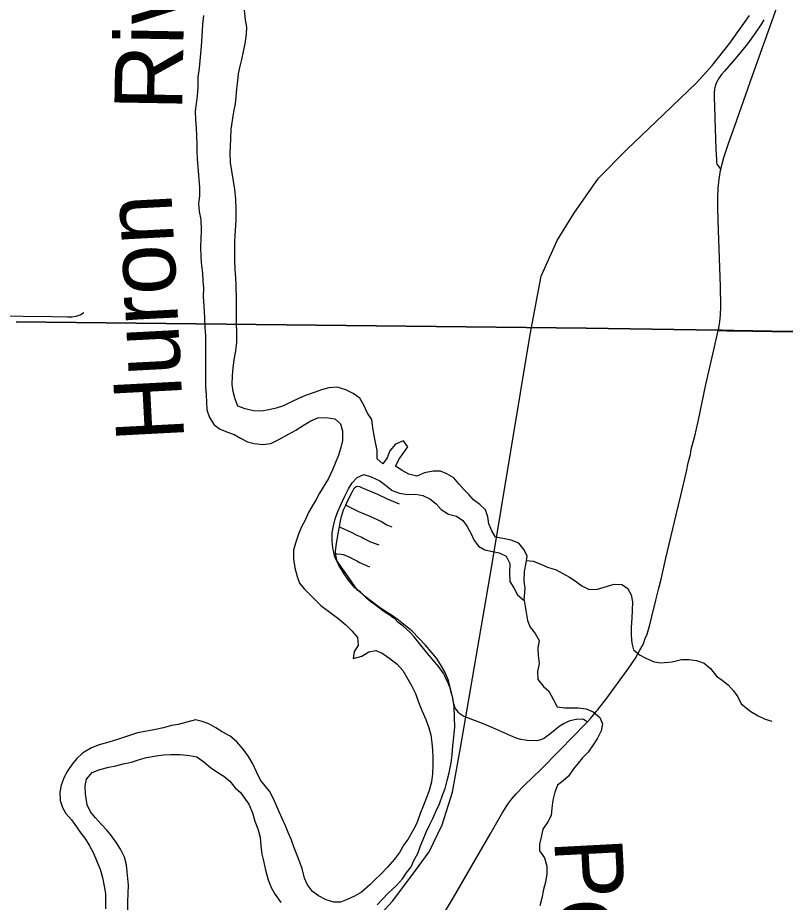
# Model space of a CAD drawing. Extents: x 0 to 34, y 0 to 22.
# Drawn here: x 3.171 to 4.241, y 16.061 to 17.296 of the extents above; entities that cross this region are included whole.
import ezdxf

# ---------------------------------------------------------------- set-up
doc = ezdxf.new("R2010")
doc.units = 0
for name, color, linetype in [('GM_X_Corporation', 7, 'Continuous'), ('GM_X_County_Road', 7, 'Continuous'), ('GM_X_Major_River', 7, 'Continuous'), ('GM_X_Major_River_Text', 7, 'Continuous'), ('GM_X_Minor_River', 7, 'Continuous'), ('GM_X_Minor_River_Text', 7, 'Continuous'), ('GM_X_Rail_Line', 7, 'Continuous'), ('GM_X_Township_Road', 7, 'Continuous')]:
    doc.layers.add(name, color=color, linetype=linetype)

msp = doc.modelspace()

# ---------------------------------------------------------------- linework, layer by layer
at = {"layer": 'GM_X_Corporation'}
for points in [[(3.1685, 16.871), (3.9635, 16.8622), (4.1478, 16.8594), (4.1529, 16.8593), (4.1603, 16.8592), (4.1696, 16.8591), (4.2224, 16.8579), (4.3406, 16.8565)], [(4.3406, 16.8565), (4.2224, 16.8579), (4.1696, 16.8591), (4.1603, 16.8592), (4.1529, 16.8593), (4.1478, 16.8594), (3.9635, 16.8622), (3.1685, 16.871)]]:
    msp.add_lwpolyline(points, dxfattribs=at)
at = {"layer": 'GM_X_County_Road'}
for points in [[(4.1515, 17.0838), (4.1532, 17.0915), (4.1558, 17.1005), (4.1626, 17.1212), (4.1709, 17.1446), (4.1959, 17.215), (4.2115, 17.259), (4.2458, 17.3557), (4.2563, 17.3849), (4.2697, 17.4231), (4.2865, 17.4699), (4.2977, 17.5022), (4.3173, 17.5613), (4.3279, 17.5905), (4.3351, 17.611), (4.3429, 17.6352)], [(4.148, 16.8588), (4.1488, 16.8623), (4.1503, 16.8714), (4.1512, 16.8805), (4.1516, 16.8927), (4.151, 16.9207), (4.1485, 16.9984), (4.1473, 17.0295), (4.1472, 17.0451), (4.1478, 17.0576), (4.1491, 17.07), (4.1512, 17.0823), (4.1515, 17.0838)], [(3.9654, 16.3127), (3.9698, 16.3176), (3.9783, 16.3276), (3.9802, 16.3298), (3.982, 16.3322), (3.9824, 16.3328), (3.991, 16.3441), (4.0223, 16.3868), (4.0326, 16.4017), (4.0387, 16.4128), (4.043, 16.4207), (4.0459, 16.4294), (4.0486, 16.4353), (4.0526, 16.4484), (4.0551, 16.4601), (4.061, 16.4827), (4.0652, 16.4996), (4.0683, 16.5122), (4.0747, 16.5413), (4.0893, 16.6017), (4.0958, 16.6288), (4.1035, 16.6622), (4.1062, 16.6745), (4.1091, 16.6862), (4.1103, 16.6934), (4.1153, 16.7117), (4.1199, 16.732), (4.1306, 16.7837), (4.1418, 16.8322), (4.148, 16.8588)], [(3.7564, 16.0303), (3.7785, 16.0677), (3.8296, 16.156), (3.8466, 16.1855), (3.8545, 16.1982), (3.8601, 16.2053), (3.866, 16.2122), (3.8767, 16.2235), (3.8901, 16.2365), (3.899, 16.245), (3.9272, 16.2738), (3.962, 16.309), (3.9654, 16.3127)]]:
    msp.add_lwpolyline(points, dxfattribs=at)
at = {"layer": 'GM_X_Major_River'}
for points in [[(3.4297, 17.2988), (3.4286, 17.2859), (3.4276, 17.2699), (3.4266, 17.2559), (3.4251, 17.2406), (3.4237, 17.225), (3.4219, 17.2125), (3.422, 17.1988), (3.421, 17.1866), (3.4199, 17.1752), (3.4184, 17.1649), (3.4189, 17.1532), (3.4197, 17.1425), (3.4202, 17.1304), (3.4207, 17.119), (3.4207, 17.1091), (3.4212, 17.098), (3.422, 17.0874), (3.4229, 17.0756), (3.4241, 17.0585), (3.4242, 17.0471), (3.4231, 17.0365), (3.424, 17.0251), (3.4263, 17.014), (3.4268, 16.9985), (3.4261, 16.9863), (3.4255, 16.9764), (3.4263, 16.9612), (3.4272, 16.9494), (3.4284, 16.9392), (3.4292, 16.9285), (3.4297, 16.9186), (3.4294, 16.9061), (3.4302, 16.8935), (3.4311, 16.8768), (3.4319, 16.8639), (3.4328, 16.8514), (3.4328, 16.8411), (3.4326, 16.8282), (3.4326, 16.8187), (3.4327, 16.8012), (3.4328, 16.7917), (3.4325, 16.781), (3.4337, 16.7689), (3.4342, 16.7594), (3.4346, 16.7483), (3.4385, 16.7377), (3.445, 16.7275), (3.453, 16.7215), (3.4633, 16.717), (3.4729, 16.714), (3.4816, 16.7087), (3.4912, 16.7035)], [(3.4733, 16.8208), (3.4751, 16.8307), (3.4765, 16.8429), (3.4764, 16.8566), (3.476, 16.868), (3.4759, 16.8786), (3.4758, 16.8908), (3.4761, 16.9014), (3.4756, 16.9224), (3.4748, 16.9326), (3.4743, 16.944), (3.4735, 16.9569), (3.4734, 16.9702), (3.4736, 16.9839), (3.4747, 16.9988), (3.4753, 17.0132), (3.4756, 17.028), (3.4748, 17.0429), (3.4735, 17.0558), (3.4719, 17.0676), (3.4695, 17.082), (3.4676, 17.0934), (3.4671, 17.1067), (3.4674, 17.1162), (3.4681, 17.1265), (3.4684, 17.1398), (3.4702, 17.1523), (3.4724, 17.1641), (3.4746, 17.1752), (3.4757, 17.1855), (3.4764, 17.1965), (3.4778, 17.2075), (3.4789, 17.217), (3.4811, 17.2277), (3.4833, 17.2372), (3.4859, 17.2486), (3.4881, 17.2593), (3.4899, 17.2726), (3.4902, 17.2825), (3.4886, 17.2928), (3.487, 17.306)], [(3.6213, 16.6157), (3.6265, 16.6267), (3.6322, 16.6382), (3.6374, 16.6462), (3.6442, 16.6538), (3.6537, 16.6581), (3.6636, 16.6547), (3.6758, 16.6491), (3.6857, 16.6419), (3.693, 16.6355), (3.7032, 16.6322), (3.7147, 16.6303), (3.7257, 16.6304), (3.7359, 16.6286), (3.7458, 16.6241), (3.7546, 16.6173), (3.7615, 16.6093), (3.7718, 16.6029), (3.7829, 16.6), (3.7916, 16.5939), (3.7978, 16.5856), (3.8032, 16.5754), (3.8074, 16.5659), (3.8135, 16.558), (3.8223, 16.5531), (3.833, 16.5505), (3.8425, 16.5486), (3.852, 16.5441), (3.8574, 16.5339), (3.8567, 16.5202), (3.8572, 16.5088), (3.8629, 16.4997), (3.868, 16.4902), (3.8771, 16.4823), (3.8785, 16.4994), (3.8773, 16.5093), (3.8776, 16.5226), (3.8802, 16.5348), (3.8816, 16.5443), (3.8774, 16.553), (3.8697, 16.5621), (3.8591, 16.5666), (3.8496, 16.5681), (3.8374, 16.5707), (3.832, 16.5794), (3.8281, 16.5892), (3.8265, 16.5991), (3.8231, 16.6086), (3.8154, 16.6161), (3.8066, 16.6226), (3.8001, 16.6301), (3.7929, 16.6373), (3.7863, 16.6449), (3.7791, 16.6532), (3.7692, 16.6588), (3.7604, 16.6626), (3.7501, 16.6629), (3.738, 16.6605), (3.7274, 16.6559), (3.7164, 16.6585), (3.7072, 16.6637), (3.6977, 16.6698), (3.7033, 16.6805), (3.7093, 16.6889), (3.715, 16.6965), (3.7088, 16.7052), (3.6978, 16.7006), (3.6899, 16.691), (3.6862, 16.6815), (3.6802, 16.6731), (3.6721, 16.6799), (3.6721, 16.692), (3.6697, 16.7027), (3.6681, 16.7125), (3.6661, 16.7232), (3.6645, 16.7346), (3.6588, 16.7437), (3.6534, 16.7547), (3.648, 16.7645), (3.6385, 16.7713), (3.6285, 16.7762), (3.6164, 16.7799), (3.6046, 16.7791), (3.5944, 16.776), (3.5845, 16.7725), (3.5724, 16.7682), (3.5622, 16.764), (3.5516, 16.759), (3.5417, 16.754), (3.5315, 16.7505), (3.5209, 16.7481), (3.5114, 16.7465), (3.4996, 16.7468), (3.4882, 16.7498), (3.4779, 16.7536), (3.474, 16.763), (3.4713, 16.7737), (3.4697, 16.7835), (3.4704, 16.7957), (3.4714, 16.8075), (3.4733, 16.8208)], [(3.4912, 16.7035), (3.5007, 16.7012), (3.5125, 16.6998), (3.5238, 16.7014), (3.5348, 16.7068), (3.5484, 16.7145), (3.5587, 16.7198), (3.5704, 16.7275), (3.5798, 16.7329), (3.5893, 16.7371), (3.6011, 16.7376), (3.6129, 16.7358), (3.6209, 16.7286), (3.624, 16.7187), (3.6237, 16.7054), (3.6215, 16.6959), (3.6182, 16.6852), (3.6141, 16.6746), (3.6099, 16.6647), (3.6043, 16.6525), (3.5919, 16.6318), (3.5871, 16.6231), (3.5814, 16.6139), (3.5766, 16.6048), (3.5717, 16.5945), (3.5664, 16.5849), (3.5623, 16.5746), (3.5582, 16.5624), (3.5556, 16.5525), (3.5554, 16.5404), (3.5573, 16.5278), (3.5605, 16.5157), (3.5639, 16.5066), (3.5701, 16.4986), (3.5777, 16.4911), (3.5846, 16.4839), (3.5938, 16.4752), (3.6098, 16.4631), (3.6175, 16.4575), (3.6285, 16.4484), (3.637, 16.4397), (3.6446, 16.4307), (3.6458, 16.4193), (3.6402, 16.4109), (3.6387, 16.4014), (3.6509, 16.4045), (3.6607, 16.4106), (3.6702, 16.4122), (3.6793, 16.4085), (3.69, 16.4013), (3.7, 16.3934), (3.708, 16.3843), (3.7149, 16.3726), (3.7207, 16.3627), (3.7257, 16.3525), (3.73, 16.3403), (3.735, 16.3278), (3.74, 16.3161), (3.7443, 16.3043), (3.747, 16.2948), (3.7482, 16.2834), (3.7494, 16.2732), (3.7499, 16.2629), (3.7496, 16.2526), (3.7493, 16.2401), (3.7478, 16.2291), (3.7449, 16.2169), (3.7404, 16.2058), (3.7363, 16.1951), (3.7322, 16.1849), (3.7277, 16.1715), (3.7228, 16.1627), (3.715, 16.1486), (3.7093, 16.141), (3.7033, 16.1307), (3.6965, 16.1211), (3.6867, 16.11), (3.6773, 16.1005), (3.6694, 16.0928), (3.6618, 16.0856), (3.6501, 16.0752), (3.6407, 16.0698), (3.6301, 16.0648), (3.621, 16.0614), (3.6115, 16.0613), (3.6012, 16.0646), (3.5905, 16.0699), (3.5821, 16.0763), (3.5748, 16.0854), (3.5706, 16.0949), (3.5675, 16.1082), (3.5609, 16.1256), (3.5566, 16.137), (3.552, 16.1491), (3.5481, 16.1582), (3.5443, 16.1677), (3.5396, 16.1779), (3.5354, 16.1874), (3.5311, 16.1969), (3.5273, 16.2064), (3.5219, 16.2162)], [(3.6723, 16.0575), (3.6791, 16.0651), (3.6877, 16.0736), (3.6991, 16.0843), (3.7074, 16.0938), (3.7126, 16.1018), (3.7194, 16.1106), (3.7235, 16.1194), (3.7288, 16.1289), (3.7325, 16.14), (3.7362, 16.1488), (3.7403, 16.1587), (3.7452, 16.1686), (3.7497, 16.1781), (3.7546, 16.1888), (3.7591, 16.1983), (3.7635, 16.2105), (3.7669, 16.2197), (3.7698, 16.2311), (3.7724, 16.2418), (3.7754, 16.2558), (3.7768, 16.2669), (3.7779, 16.2794), (3.7793, 16.2916), (3.7803, 16.3061), (3.7802, 16.319), (3.7794, 16.3342), (3.7774, 16.3482), (3.7715, 16.3706), (3.7665, 16.3828), (3.7607, 16.393), (3.755, 16.4017), (3.7473, 16.4108), (3.7397, 16.4199), (3.7305, 16.4297), (3.7209, 16.4395), (3.7114, 16.4474), (3.7018, 16.4546), (3.6934, 16.461), (3.6839, 16.467), (3.6751, 16.4731), (3.664, 16.4814), (3.656, 16.4874), (3.6487, 16.4938), (3.6411, 16.4998), (3.6323, 16.5108), (3.625, 16.5207), (3.6185, 16.5313), (3.6131, 16.5426), (3.6103, 16.5555), (3.6095, 16.565), (3.6094, 16.5768), (3.6113, 16.5863), (3.6135, 16.5962), (3.6172, 16.6065), (3.6213, 16.6157)], [(3.5219, 16.2162), (3.5154, 16.2242), (3.5096, 16.2317), (3.5038, 16.2431), (3.4988, 16.2541), (3.4927, 16.2647), (3.4854, 16.2749), (3.4762, 16.2851), (3.467, 16.2927), (3.456, 16.2987), (3.4472, 16.3043), (3.4373, 16.31), (3.4281, 16.3134), (3.4186, 16.3156), (3.4065, 16.3125), (3.3947, 16.3093), (3.3853, 16.3078), (3.3743, 16.3046), (3.3629, 16.3023), (3.3507, 16.2999), (3.3378, 16.2976), (3.3238, 16.2929), (3.3098, 16.2883), (3.2977, 16.2844), (3.2844, 16.2809), (3.2738, 16.2766), (3.2609, 16.269), (3.253, 16.2617), (3.2466, 16.254), (3.2406, 16.2449), (3.2357, 16.2357), (3.2312, 16.2247), (3.2294, 16.2148), (3.2302, 16.203), (3.233, 16.1935), (3.238, 16.1848), (3.2456, 16.1761), (3.2529, 16.1662), (3.259, 16.1575), (3.2652, 16.1492), (3.2706, 16.1409), (3.2763, 16.1295), (3.2817, 16.117), (3.2856, 16.1071), (3.2891, 16.0954), (3.2915, 16.0836), (3.2931, 16.0734), (3.2931, 16.0616), (3.2932, 16.0521)], [(3.2979, 16.2494), (3.3074, 16.2514), (3.318, 16.2541), (3.3294, 16.2568), (3.3408, 16.2603), (3.3502, 16.2631), (3.3639, 16.2654), (3.3741, 16.267), (3.3844, 16.2674), (3.3973, 16.2672), (3.4102, 16.2657), (3.4205, 16.2639), (3.4304, 16.2571), (3.4396, 16.2492), (3.4499, 16.242), (3.4583, 16.2371), (3.4667, 16.2303), (3.474, 16.2209), (3.4813, 16.2141), (3.4931, 16.1978), (3.4982, 16.186), (3.5017, 16.1743), (3.5059, 16.1637), (3.509, 16.1519), (3.5099, 16.1397), (3.5115, 16.1283), (3.5134, 16.1188), (3.5162, 16.1059), (3.5201, 16.0923), (3.5243, 16.0817), (3.5297, 16.0718), (3.5378, 16.0608)], [(3.3244, 16.0504), (3.3243, 16.0618), (3.325, 16.0739), (3.3253, 16.085), (3.3236, 16.1036), (3.3224, 16.1135), (3.3197, 16.1241), (3.3143, 16.1351), (3.3085, 16.1438), (3.3016, 16.1536), (3.2955, 16.1612), (3.2875, 16.1695), (3.2794, 16.179), (3.2725, 16.1873), (3.2675, 16.1971), (3.2651, 16.2123), (3.265, 16.2234), (3.2665, 16.2329), (3.2744, 16.242), (3.2854, 16.2463), (3.2979, 16.2494)]]:
    msp.add_lwpolyline(points, dxfattribs=at)
at = {"layer": 'GM_X_Minor_River'}
for points in [[(3.8807, 16.5379), (3.89, 16.5372), (3.9003, 16.533), (3.9098, 16.5289), (3.922, 16.5248), (3.9312, 16.5199), (3.9403, 16.515), (3.9483, 16.5098), (3.9575, 16.5026), (3.9678, 16.4977), (3.9796, 16.4978), (3.9936, 16.5021), (4.0027, 16.5052), (4.0133, 16.5045), (4.0214, 16.4992), (4.0267, 16.4901), (4.0283, 16.4802), (4.028, 16.4688), (4.0273, 16.4574), (4.0263, 16.4449), (4.0264, 16.4335), (4.0272, 16.4228), (4.0299, 16.4133), (4.0383, 16.4065), (4.0471, 16.4016), (4.0585, 16.3964), (4.068, 16.3953), (4.0836, 16.3966), (4.0965, 16.3997), (4.1068, 16.4001), (4.1174, 16.3987), (4.1285, 16.3949), (4.1372, 16.3874), (4.1457, 16.3768), (4.1533, 16.3711), (4.1617, 16.3643), (4.169, 16.356), (4.1751, 16.3477), (4.1801, 16.3382), (4.1935, 16.3273), (4.2034, 16.3213), (4.2133, 16.3168), (4.2225, 16.3138)], [(3.8771, 16.4823), (3.8819, 16.4542), (3.8857, 16.4451), (3.8926, 16.436), (3.898, 16.4262), (3.8962, 16.4163), (3.8966, 16.4056), (3.8982, 16.3942), (3.896, 16.3832), (3.8965, 16.3718), (3.9042, 16.3623), (3.9114, 16.3559), (3.918, 16.3438), (3.9234, 16.3336), (3.934, 16.3325), (3.9435, 16.3326), (3.953, 16.3322), (3.9636, 16.3312), (3.9736, 16.3267), (3.9827, 16.3187), (3.9866, 16.31), (3.9848, 16.3001), (3.9795, 16.2902), (3.9735, 16.2807), (3.9663, 16.2707), (3.9588, 16.2627), (3.9524, 16.2551), (3.946, 16.2474), (3.9392, 16.2371), (3.9317, 16.2306), (3.9237, 16.2245), (3.92, 16.2146), (3.9174, 16.2035), (3.916, 16.1925), (3.9149, 16.1822), (3.91, 16.1734), (3.9033, 16.1631), (3.9011, 16.1521), (3.8985, 16.1422), (3.8985, 16.1327), (3.9054, 16.1232), (3.9089, 16.1114), (3.9086, 16.1008), (3.9068, 16.089), (3.9042, 16.0791), (3.9017, 16.0669), (3.8991, 16.0563)]]:
    msp.add_lwpolyline(points, dxfattribs=at)
at = {"layer": 'GM_X_Rail_Line'}
msp.add_lwpolyline([(3.6692, 16.0362), (3.6936, 16.0627), (3.7206, 16.0984), (3.7446, 16.1316), (3.7628, 16.1691), (3.7771, 16.2147), (3.7883, 16.2764), (3.8317, 16.5279), (3.8858, 16.8536), (3.9009, 16.9349), (3.9234, 16.9845), (3.9464, 17.0221), (3.9809, 17.0714), (4.0208, 17.1123), (4.0609, 17.1502), (4.1174, 17.2048), (4.1396, 17.229), (4.164, 17.2599), (4.1914, 17.2987)], dxfattribs=at)
at = {"layer": 'GM_X_Township_Road'}
for points in [[(4.2113, 17.2924), (4.2081, 17.2871), (4.1995, 17.2741), (4.1887, 17.2589), (4.181, 17.2491), (4.1689, 17.2349), (4.1565, 17.221), (4.1526, 17.2162), (4.1493, 17.2117), (4.1474, 17.2085), (4.1452, 17.2042), (4.1437, 17.2002), (4.1427, 17.1962), (4.1421, 17.1904), (4.1421, 17.184), (4.1426, 17.1717), (4.1437, 17.1406), (4.1448, 17.1127), (4.1454, 17.0972), (4.1453, 17.094), (4.146, 17.0911), (4.1502, 17.0855), (4.1515, 17.0838)], [(2.8957, 16.8756), (2.9018, 16.8764), (2.92, 16.8805), (2.9262, 16.8815), (2.9293, 16.8819), (2.9356, 16.8822), (2.976, 16.8818), (3.0444, 16.8808), (3.1159, 16.8798), (3.1375, 16.8796), (3.2183, 16.8784), (3.2401, 16.8781), (3.2462, 16.8782), (3.2492, 16.8784), (3.2522, 16.8789), (3.255, 16.8798), (3.2577, 16.881), (3.2629, 16.8842)], [(4.148, 16.8588), (4.1531, 16.8588), (4.1605, 16.8587), (4.1698, 16.8586), (4.2226, 16.8574), (4.3408, 16.8559), (4.3781, 16.855), (4.379, 16.855)], [(3.6283, 16.6151), (3.6304, 16.6199), (3.6373, 16.6336), (3.6385, 16.6364), (3.6402, 16.639), (3.6423, 16.6409), (3.6448, 16.6417), (3.6476, 16.6411), (3.6504, 16.6397), (3.6669, 16.6328), (3.6724, 16.6305), (3.6861, 16.6239), (3.6973, 16.6194), (3.7028, 16.6169)], [(3.6194, 16.5849), (3.621, 16.5935), (3.6225, 16.5995), (3.6254, 16.6086), (3.6283, 16.6151)], [(3.6283, 16.6151), (3.6322, 16.6132), (3.646, 16.6062), (3.662, 16.5999), (3.6783, 16.5925), (3.6856, 16.588), (3.6928, 16.5852)], [(3.6142, 16.5473), (3.6142, 16.5507), (3.6149, 16.5584), (3.6176, 16.5759), (3.6194, 16.5849)], [(3.6194, 16.5849), (3.6217, 16.5839), (3.6357, 16.5776), (3.644, 16.5735), (3.6506, 16.5705), (3.6524, 16.5692), (3.663, 16.5642), (3.6745, 16.5597)], [(3.6142, 16.5473), (3.616, 16.5473), (3.6218, 16.5471), (3.6247, 16.5464), (3.6276, 16.5455), (3.6334, 16.5429), (3.6446, 16.5372), (3.6468, 16.5358), (3.6616, 16.5291)], [(3.9654, 16.3127), (3.9635, 16.314), (3.9601, 16.3162), (3.9566, 16.3167), (3.9504, 16.3163), (3.9473, 16.3158), (3.9413, 16.3143), (3.9384, 16.3133), (3.9356, 16.312), (3.9328, 16.3106), (3.9276, 16.3072), (3.9203, 16.3015), (3.913, 16.2957), (3.9081, 16.292), (3.9055, 16.2902), (3.9028, 16.2887), (3.8999, 16.2876), (3.8969, 16.2869), (3.8938, 16.2865), (3.8815, 16.2867), (3.8785, 16.2871), (3.8727, 16.2882), (3.8674, 16.2898), (3.8587, 16.2932), (3.8333, 16.3047), (3.819, 16.3107), (3.7957, 16.3193), (3.7929, 16.3205), (3.7902, 16.322), (3.7877, 16.3239), (3.7855, 16.3261), (3.7837, 16.3286), (3.781, 16.3318), (3.7792, 16.3381), (3.7777, 16.3466), (3.7754, 16.3537), (3.774, 16.3603), (3.7727, 16.3632), (3.7715, 16.3662), (3.7677, 16.3744), (3.7665, 16.3772), (3.7651, 16.3797), (3.7583, 16.3896), (3.7505, 16.399), (3.7424, 16.4084), (3.7366, 16.4153), (3.7238, 16.4313), (3.7176, 16.4381), (3.7131, 16.4424), (3.7084, 16.4464), (3.7012, 16.4519), (3.6972, 16.4561), (3.6947, 16.4578), (3.6901, 16.4615), (3.6801, 16.4678), (3.6752, 16.4714), (3.668, 16.477), (3.6631, 16.4805), (3.6579, 16.4849), (3.6519, 16.4909), (3.6449, 16.4968), (3.6371, 16.5072), (3.6312, 16.5161), (3.6219, 16.5291), (3.6165, 16.5371), (3.6143, 16.5453), (3.6142, 16.5473)]]:
    msp.add_lwpolyline(points, dxfattribs=at)

# ---------------------------------------------------------------- texts
at = {"layer": 'GM_X_Major_River_Text'}
msp.add_text('Huron', height=0.09475, rotation=93.0009, dxfattribs=at).set_placement((3.4032, 16.7068))
at = {"layer": 'GM_X_Minor_River_Text'}
for s, rotation, p in [('River', 89.0015, (3.4002, 17.1653)), ('Poncas', 273.0016, (3.9191, 16.1483))]:
    msp.add_text(s, height=0.09475, rotation=rotation, dxfattribs=at).set_placement(p)

doc.saveas('drawing.dxf')
